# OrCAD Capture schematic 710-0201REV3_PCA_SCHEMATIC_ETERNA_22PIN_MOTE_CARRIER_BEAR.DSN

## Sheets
1 01) Title: title: PCA SCHEMATIC, ETERNA 22-PIN WH MOTE, BEAR; rev: 03; note: 710-0201
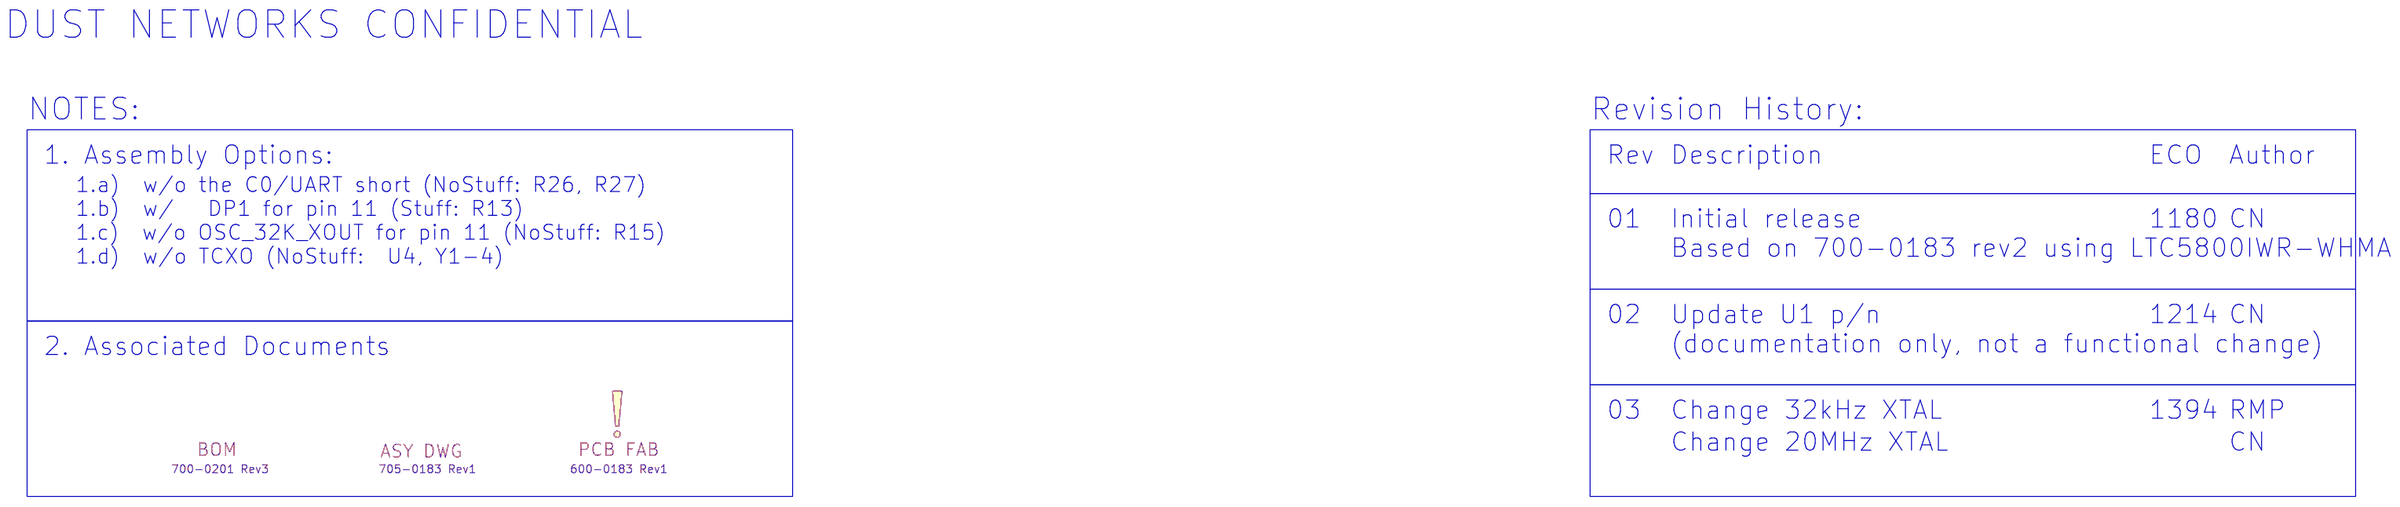
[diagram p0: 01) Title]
2 02) OSKI Mote: size Custom
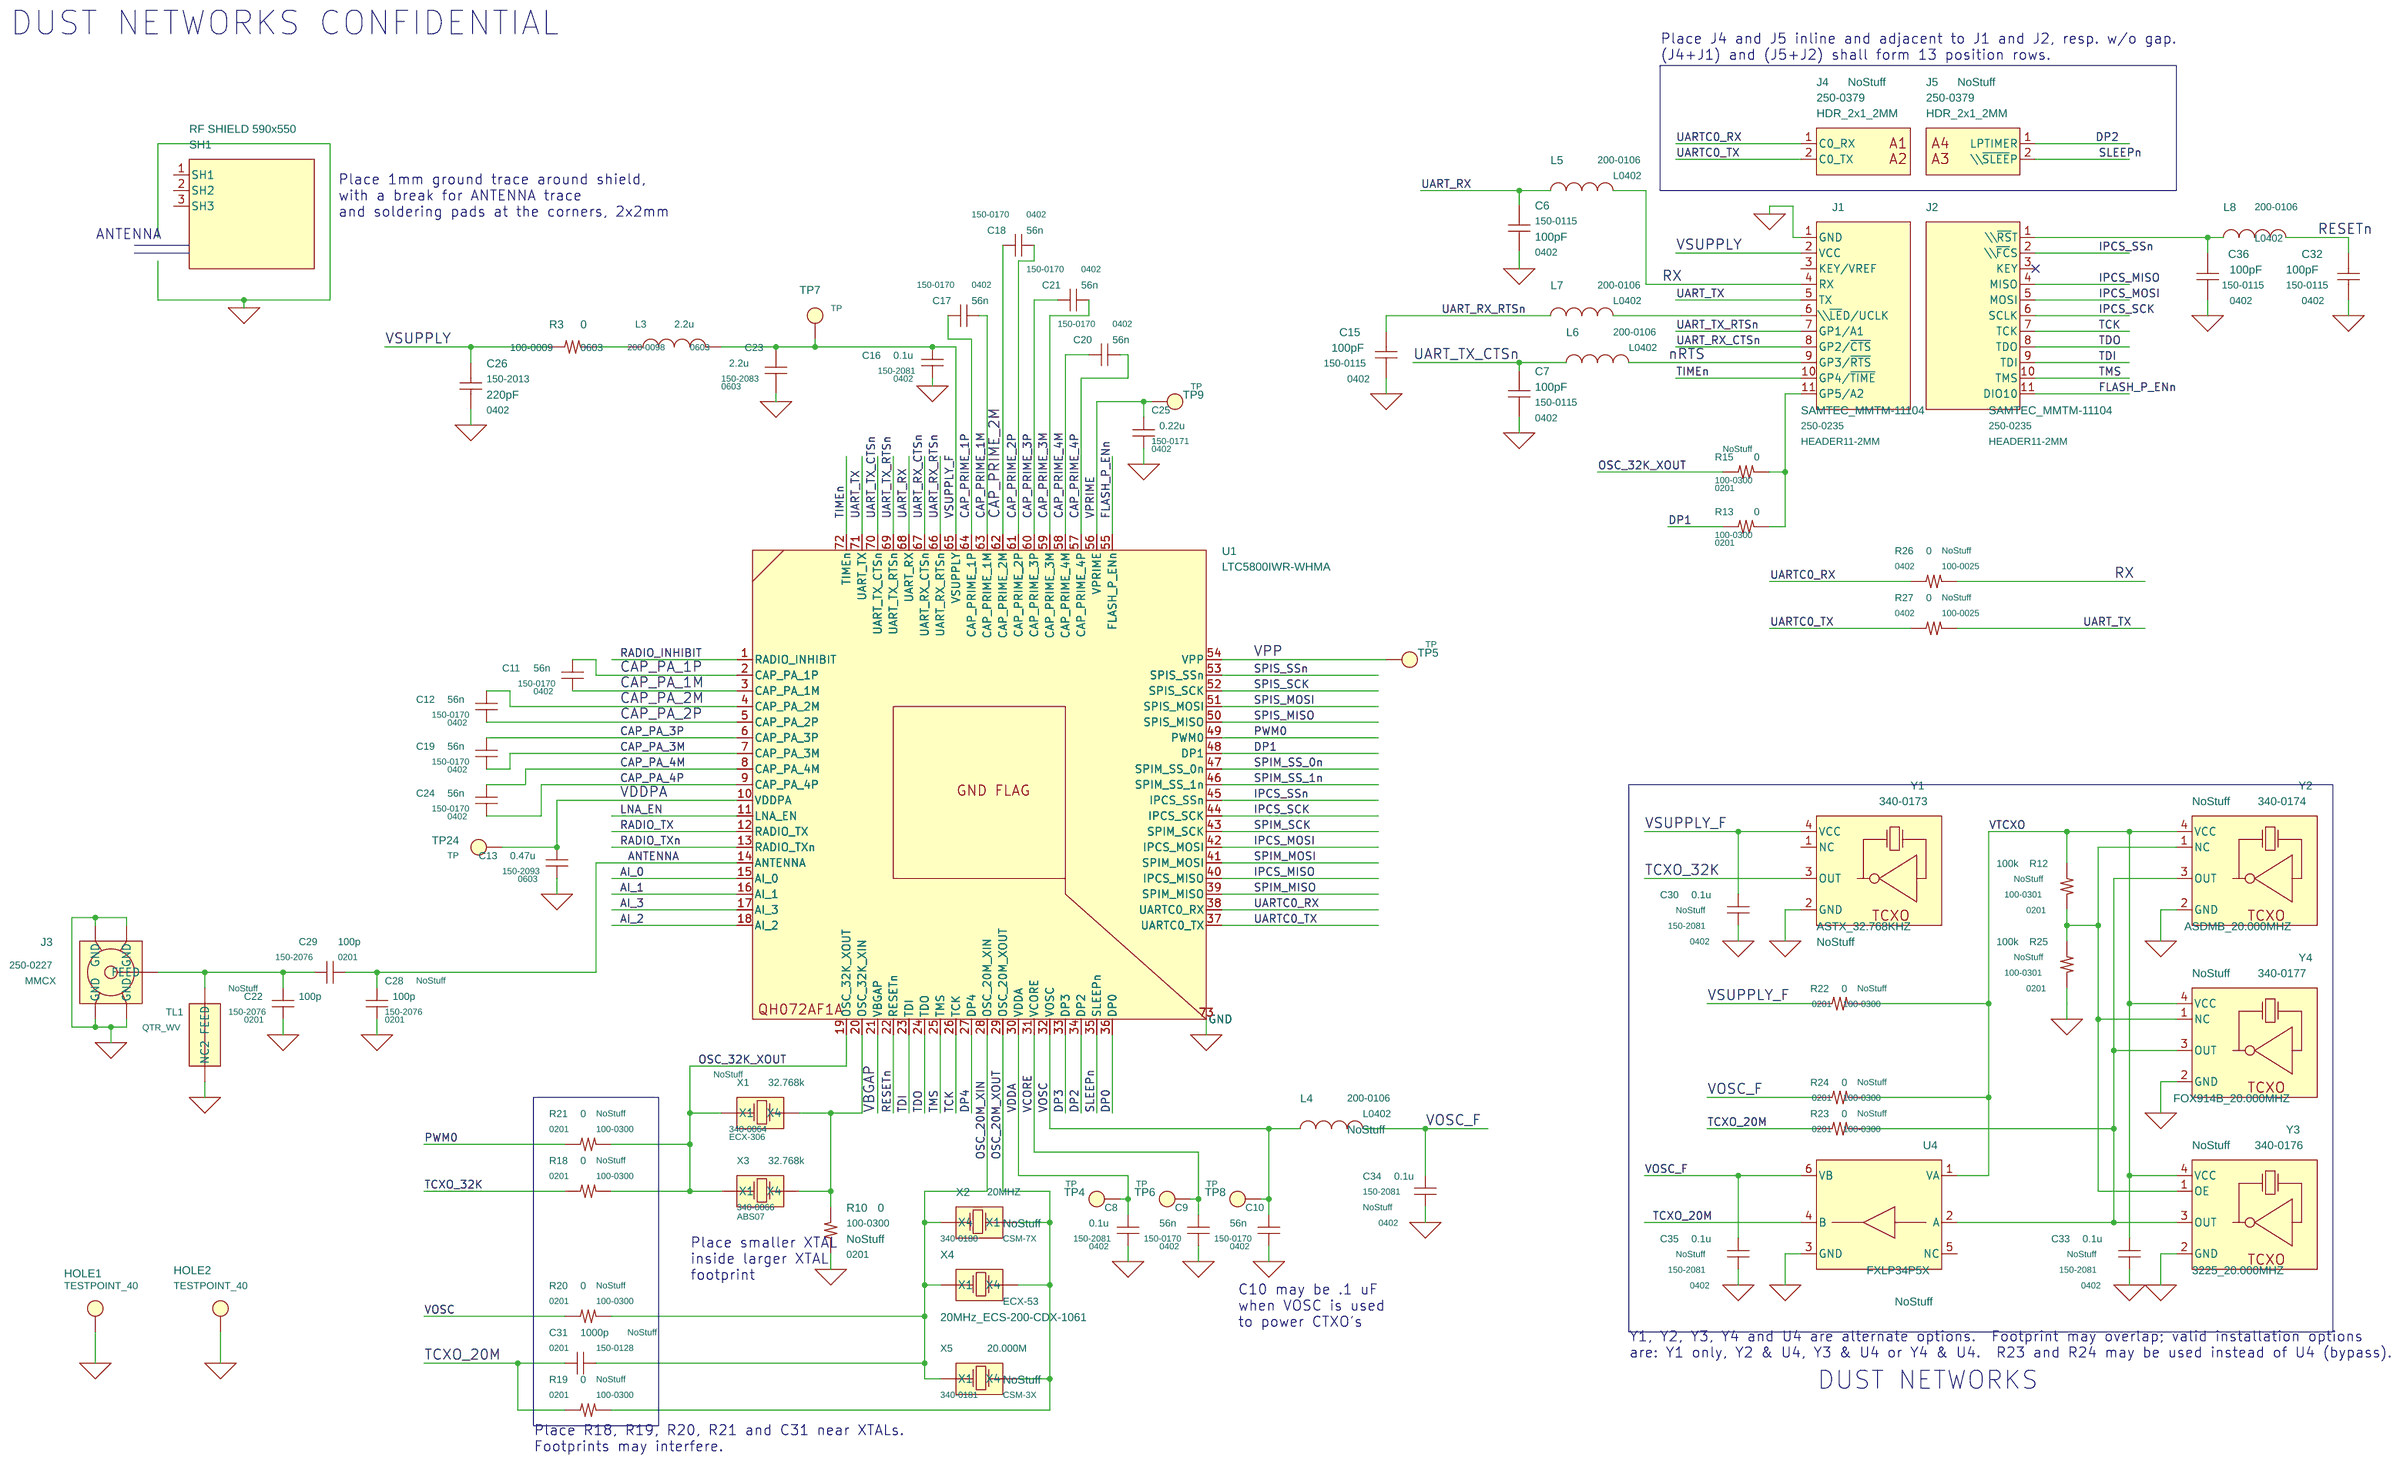
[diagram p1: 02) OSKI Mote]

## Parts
sheet 01) Title
WARNINGL11  CALLOUT_PCB_FAB
WARNINGL12  CALLOUT_BOM
WARNINGL13  CALLOUT_ASSY_DWG
sheet 02) OSKI Mote
C6  100pF  [0402]
C7  100pF  [0402]
C8  0.1u  [0402]
C9  56n  [0402]
C10  56n  [0402]
C11  56n  [0402]
C12  56n  [0402]
C13  0.47u  [0603]
C15  100pF  [0402]
C16  0.1u  [0402]
C17  56n  [0402]
C18  56n  [0402]
C19  56n  [0402]
C20  56n  [0402]
C21  56n  [0402]
C22  100p  [0201]
C23  2.2u  [0603]
C24  56n  [0402]
C25  0.22u  [0402]
C26  220pF  [0402]
C28  100p  [0201]
C29  100p  [0201]
C30  0.1u  [0402]
C31  1000p  [0201]
C32  100pF  [0402]
C33  0.1u  [0402]
C34  0.1u  [0402]
C35  0.1u  [0402]
C36  100pF  [0402]
HOLE1  HOLE  [TESTPOINT_40]
HOLE2  HOLE  [TESTPOINT_40]
J1  SAMTEC_MMTM-11104  [HEADER11-2MM]
J2  SAMTEC_MMTM-11104  [HEADER11-2MM]
J3  MMCX/U.FL  [MMCX]
J4  HDR_2x1_2MM  [HDR2X1PTH2MM_RND]
J5  HDR_2x1_2MM  [HDR2X1PTH2MM_RND]
L3  2.2u  [0603]
L4  200mA_600mO  [L0402]
L5  200mA_600mO  [L0402]
L6  200mA_600mO  [L0402]
L7  200mA_600mO  [L0402]
L8  200mA_600mO  [L0402]
R3  0  [0603]
R10  0  [0201]
R12  100k  [0201]
R13  0  [0201]
R15  0  [0201]
R18  0  [0201]
R19  0  [0201]
R20  0  [0201]
R21  0  [0201]
R22  0  [0201]
R23  0  [0201]
R24  0  [0201]
R25  100k  [0201]
R26  0  [0402]
R27  0  [0402]
SH1  RF SHIELD 590x550  [SHLD_BEAR]
TL1  FR05  [QTR_WV]
TP4  TP 35Mil  [TP]
TP5  TP 35Mil  [TP]
TP6  TP 35Mil  [TP]
TP7  TP 35Mil  [TP]
TP8  TP 35Mil  [TP]
TP9  TP 35Mil  [TP]
TP24  TP 35Mil  [TP]
U1  LTC5800IWR-WHMA  [QH072AF1A]
U4  FXLP34P5X  [SC70]
X1  32.768k  [ECX-306]
X2  20MHZ  [CSM-7X]
X3  32.768k  [ABS07]
X4  20MHz_ECS-200-CDX-1061  [ECX-53]
X5  20.000M  [CSM-3X]
Y1  ASTX_32.768KHZ  [XASTX7050SM]
Y2  ASDMB_20.000MHZ  [XASDMB2520SM]
Y3  3225_20.000MHZ  [XTAL3225SM]
Y4  FOX914B_20.000MHZ  [XFOX5032SM]

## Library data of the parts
WARNINGL11 = CALLOUT_PCB_FAB: Part Number: 600-0183 Rev1
WARNINGL12 = CALLOUT_BOM: Part Number: 700-0201 Rev3
WARNINGL13 = CALLOUT_ASSY_DWG: Part Number: 705-0183 Rev1
C6 C7 C15 C32 C36 = CAP_NP_5: P/N #1: GRM188F51A475ZE20; Part Number: 150-0115; Rating: 50V; Tolerance: 5%
C8 = C_Generic: Mfg #1: Murata; Mfg #2: GRM033R60J104KE19D; P/N #1: 150-FIX; Part Number: 150-2081; Rating: 16V; Tolerance: 10%
C9 C10 = C_Generic: Mfg #1: Murata; Mfg #2: GRM033R60J104KE19D; P/N #1: 150-FIX; Part Number: 150-0170; Rating: 16V; Tolerance: 10%
C11 C12 C17-C21 C24 = C_Generic: Mfg #1: Murata; Mfg #2: GRM033R60J104KE19D; P/N #1: 150-2081; Part Number: 150-0170; Rating: 16V; Tolerance: 10%
C13 = C_Generic: Mfg #1: Murata; Mfg #2: GRM033R60J104KE19D; P/N #1: 150-2081; Part Number: 150-2093; Rating: 16V; Tolerance: 10%
C16 = C_Generic: Mfg #1: Murata; Mfg #2: GRM033R60J104KE19D; P/N #1: 150-2081; Part Number: 150-2081; Rating: 16V; Tolerance: 10%
C22 C28 = C_Generic: Mfg #1: Murata; Mfg #2: GRM033R60J104KE19D; P/N #1: 150-FIX; Part Number: 150-2076; Rating: 16V; Stuff: NoStuff; Tolerance: 10%
C23 = CAP_NP_5: P/N #1: GRM188R71A225KE15D; Part Number: 150-2083; Rating: 10V; Tolerance: 10%
C25 = C_Generic: Mfg #1: Murata; Mfg #2: GRM033R60J104KE19D; P/N #1: 150-FIX; Part Number: 150-0171; Rating: 16V; Tolerance: 10%
C26 = CAP_NP_5: P/N #1: GRM188F51A475ZE20; Part Number: 150-2013; Rating: 6.3V; Tolerance: 20%
C29 = C_Generic: Mfg #1: Murata; Mfg #2: GRM033R60J104KE19D; P/N #1: 150-FIX; Part Number: 150-2076; Rating: 16V; Tolerance: 10%
C30 C33-C35 = C_Generic: Mfg #1: Murata; Mfg #2: GRM033R60J104KE19D; P/N #1: 150-2081; Part Number: 150-2081; Rating: 16V; Stuff: NoStuff; Tolerance: 10%
C31 = C_Generic: Mfg #1: Murata; Mfg #2: GRM033R60J104KE19D; P/N #1: 150-FIX; Part Number: 150-0128; Rating: 16V; Stuff: NoStuff; Tolerance: 10%
HOLE1 HOLE2 = Mighty_GND_0: Manuf PN: NA
J1 = hdr1x8_5: Manuf PN: Samtec MTMM-111-04-S-S-175-3; Part Number: 250-0235
J2 = hdr1x8_4: Manuf PN: Samtec MTMM-111-04-S-S-175-3; Part Number: 250-0235
J3 = Hirose_EFL_4: CONN MMCX JACK STR PCB .115" GOLD; Alternate: Johnson 135-3701-301 (MMCX RA), JST AYU1-1P-02676-120 (U.FL); Dist PN: Digikey J597-ND; Manuf PN: Johnson 135-3701-201; Part Number: 250-0227
J4 = HDR_2x1_2MM_PTHRND_A1A2: Color: Default; Part Number: 250-0379; Stuff: NoStuff
J5 = HDR_2x1_2MM_PTHRND_A4A3: Color: Default; Part Number: 250-0379; Stuff: NoStuff
L3 = INDUCTOR: P/N #1: LQM18FN2R2K00; Part Number: 200-0098; Tolerance: 10%
L4 = IND_FERRITE_200MA_470OHM_0402: Part Number: 200-0106; Stuff: NoStuff
L5-L8 = IND_FERRITE_200MA_470OHM_0402: Part Number: 200-0106
R3 = R_Small: P/N #1: 100-0058; Part Number: 100-0009; Rating: 1/16 W; Tolerance: 5%
R10 = R_Small: P/N #1: 100-0058; Part Number: 100-0300; Rating: 1/16 W; Stuff: NoStuff; Tolerance: 5%
R12 R25 = R_Small: Mfg #1: Panasonic; Mfg #2: ERJ-1GEJ104C; P/N #1: 100-0048; Part Number: 100-0301; Rating: 1/16 W; Stuff: NoStuff; Tolerance: 5%
R13 = R_Small: Mfg #1: Panasonic; Mfg #2: ERJ-1GEJ104C; P/N #1: 100-0048; Part Number: 100-0300; Rating: 1/16 W; Tolerance: 5%
R15 R18-R24 = R_Small: Mfg #1: Panasonic; Mfg #2: ERJ-1GEJ104C; P/N #1: 100-0048; Part Number: 100-0300; Rating: 1/16 W; Stuff: NoStuff; Tolerance: 5%
R26 R27 = R_Small: Mfg #1: Yageo; Mfg #2: RC0402JR-070RL; P/N #1: 100-0048; Part Number: 100-0025; Rating: 1/16 W; Stuff: NoStuff; Tolerance: 5%
SH1 = BEAR_SHIELD
TL1 = Hirose_EFL_8: CONN MMCX JACK STR PCB .115" GOLD; Alternate: Johnson 135-3701-301 (MMCX RA), JST AYU1-1P-02676-120 (U.FL); Dist PN: Digikey J597-ND; Manuf PN: Johnson 135-3701-201
TP4-TP9 TP24 = TP35: Dist PN: NA; Manuf PN: NA
U1 = LTC5800IWR-WHMA
U4 = FXLP34P5X_SC70: Stuff: NoStuff
X1 = CITIZEN4_0: Mfg #1: Suntsu; Part Number: 340-0064; Stuff: NoStuff
X2 = XTAL_20.000MHZ_CTRL_ECS-CSM7X: CRYSTAL, 20.000MHZ, 10PF, +/-10PPM, +/-30PPM STAB, CONTROLED T CURVE, 13.2X4.8X4.3MM, CSM-7X, SMT, ECS-200-CDX-0912; Part Number: 340-0180; Stuff: NoStuff
X3 = CITIZEN4_0: Mfg #1: Suntsu; Part Number: 340-0066
X4 = XTAL_20.000MHZ_ECS-200-CDX-1061
X5 = XTAL_20.000MHZ_CRTL_ECS-CSM3X: CRYSTAL, 20.000MHZ, 10PF, +/-10PPM, +/-30PPM STAB, CONTROLED T CURVE, 7.6X4.1X2.3MM, CSM-3X, SMT, ECS-200-CDX-0914; Part Number: 340-0181; Stuff: NoStuff
Y1 = TCXO_32.768KHZ_ASTX-H08K_SM7X5: Part Number: 340-0173; Stuff: NoStuff
Y2 = TCXO_20.000MHZ_MEMS_ASDMB-XY: Part Number: 340-0174; Stuff: NoStuff
Y3 = TCXO_20.000MHZ_XTAL3225SM: OSC, TCXO 20.000MHZ, 5PPM, -40/85C, 3.3V, SMT, 2.5x3.2MM, ECS-2532HS (ALT: FOX923, ABRACON ASEMP); Part Number: 340-0176; Stuff: NoStuff
Y4 = TCXO_20.000MHZ_FOX914B: Part Number: 340-0177; Stuff: NoStuff

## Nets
GND_SIGNAL: C6.1 C7.1 C8.2 C9.2 C10.2 C13.2 C15.1 C16.2 C22.2 C23.2 C25.2 C26.1 C28.2 C30.2 C32.1 C33.2 C34.2 C35.2 C36.1 HOLE1.1(TP) HOLE2.1(TP) J1.1(GND) J3.2(GND) J3.3(GND) J3.4(GND) J3.5(GND) R10.1 R25.1 TL1.2(NC2) U1.73(GND) U4.3(GND) Y1.2(GND) Y2.2(GND) Y3.2(GND) Y4.2(GND)
VDDA: C8.1 TP4.1(TP) U1.30(VDDA)
VDDPA: C13.1 TP24.1(TP) U1.10(VDDPA)
AI_0: U1.15(AI_0)
AI_1: U1.16(AI_1)
AI_2: U1.18(AI_2)
AI_3: U1.17(AI_3)
ANTENNA: C28.1 C29.2 U1.14(ANTENNA)
CAP_PA_1M: C11.2 U1.3(CAP_PA_1M)
CAP_PA_1P: C11.1 U1.2(CAP_PA_1P)
CAP_PA_2M: C12.1 U1.4(CAP_PA_2M)
CAP_PA_2P: C12.2 U1.5(CAP_PA_2P)
CAP_PA_3M: C19.2 U1.7(CAP_PA_3M)
CAP_PA_3P: C19.1 U1.6(CAP_PA_3P)
CAP_PA_4M: C24.1 U1.8(CAP_PA_4M)
CAP_PA_4P: C24.2 U1.9(CAP_PA_4P)
CAP_PRIME_1M: C17.2 U1.63(CAP_PRIME_1M)
CAP_PRIME_1P: C17.1 U1.64(CAP_PRIME_1P)
CAP_PRIME_2M: C18.1 U1.62(CAP_PRIME_2M)
CAP_PRIME_2P: C18.2 U1.61(CAP_PRIME_2P)
CAP_PRIME_3M: C21.2 U1.59(CAP_PRIME_3M)
CAP_PRIME_3P: C21.1 U1.60(CAP_PRIME_3P)
CAP_PRIME_4M: C20.1 U1.58(CAP_PRIME_4M)
CAP_PRIME_4P: C20.2 U1.57(CAP_PRIME_4P)
DP0: U1.36(DP0)
DP1: R13.1 U1.48(DP1)
DP2: J5.1(LPTIMER) U1.34(DP2)
DP3: U1.33(DP3)
DP4: U1.27(DP4)
FLASH_P_ENn: J2.11(DIO10) U1.55(FLASH_P_ENn)
IPCS_MISO: J2.4(MISO) U1.40(IPCS_MISO)
IPCS_MOSI: J2.5(MOSI) U1.42(IPCS_MOSI)
IPCS_SCK: J2.6(SCLK) U1.44(IPCS_SCK)
IPCS_SSn: J2.2(\\~{FC}S) U1.45(IPCS_SSn)
LNA_EN: U1.11(LNA_EN)
nRTS: J1.9(GP3/~{RTS}) L6.2
OSC_20M_XIN: C31.2 R20.2 U1.28(OSC_20M_XIN) X2.2(X4) X4.1(X1) X5.1(X1)
OSC_20M_XOUT: R19.2 U1.29(OSC_20M_XOUT) X2.1(X1) X4.2(X4) X5.2(X4)
OSC_32K_XOUT: R15.1 R18.2 R21.2 U1.19(OSC_32K_XOUT) X1.1(X1) X3.1(X1)
PWM0: R21.1 U1.49(PWM0)
RADIO_INHIBIT: U1.1(RADIO_INHIBIT)
RADIO_TX: U1.12(RADIO_TX)
RADIO_TXn: U1.13(RADIO_TXn)
RESETn: C32.2 L8.2 U1.22(RESETn)
RX: J1.4(RX) L5.2 R26.2
SLEEPn: J5.2(\\~{SLEE}P) U1.35(SLEEPn)
SPIM_MISO: U1.39(SPIM_MISO)
SPIM_MOSI: U1.41(SPIM_MOSI)
SPIM_SCK: U1.43(SPIM_SCK)
SPIM_SS_0n: U1.47(SPIM_SS_0n)
SPIM_SS_1n: U1.46(SPIM_SS_1n)
SPIS_MISO: U1.50(SPIS_MISO)
SPIS_MOSI: U1.51(SPIS_MOSI)
SPIS_SCK: U1.52(SPIS_SCK)
SPIS_SSn: U1.53(SPIS_SSn)
TCK: J2.7(TCK) U1.26(TCK)
TCXO_20M: C31.1 R19.1 R23.1 U4.4(B)
TCXO_32K: R18.1 Y1.3(OUT)
TDI: J2.9(TDI) U1.23(TDI)
TDO: J2.8(TDO) U1.24(TDO)
TIMEn: J1.10(GP4/~{TIME}) U1.72(TIMEn)
TMS: J2.10(TMS) U1.25(TMS)
UART_RX: C6.2 L5.1 U1.68(UART_RX)
UART_RX_CTSn: J1.8(GP2/~{CTS}) U1.67(UART_RX_CTSn)
UART_RX_RTSn: C15.2 L7.1 U1.66(UART_RX_RTSn)
UART_TX: J1.5(TX) R27.2 U1.71(UART_TX)
UART_TX_CTSn: C7.2 L6.1 U1.70(UART_TX_CTSn)
UART_TX_RTSn: J1.7(GP1/A1) U1.69(UART_TX_RTSn)
UARTC0_RX: J4.1(C0_RX) R26.1 U1.38(UARTC0_RX)
UARTC0_TX: J4.2(C0_TX) R27.1 U1.37(UARTC0_TX)
VBGAP: U1.21(VBGAP)
VCORE: C9.1 TP6.1(TP) U1.31(VCORE)
VOSC: C10.1 L4.1 R20.1 TP8.1(TP) U1.32(VOSC)
VOSC_F: C34.1 C35.1 L4.2 R24.1 U4.6(VB)
VPP: TP5.1(TP) U1.54(VPP)
VPRIME: C25.1 TP9.1(TP) U1.56(VPRIME)
VSUPPLY: C26.2 J1.2(VCC) R3.1
VSUPPLY_F: C16.1 C23.1 C30.1 L3.2 R22.1 TP7.1(TP) U1.65(VSUPPLY) Y1.4(VCC)
VTCXO: C33.1 R12.2 R22.2 R24.2 U4.1(VA) Y2.4(VCC) Y3.4(VCC) Y4.4(VCC)
N17907381: J1.11(GP5/A2) R13.2 R15.2
N19117367: L3.1 R3.2
N19117458: R10.2 U1.20(OSC_32K_XIN) X1.2(X4) X3.2(X4)
N19117741: C22.1 C29.1 J3.1(FEED) TL1.1(FEED)
N19224637: J1.6(\\~{LE}D/UCLK) L7.2
N19546026: R23.2 U4.2(A) Y2.3(OUT) Y3.3(OUT) Y4.3(OUT)
N19766592: R12.1 R25.2 Y2.1(NC) Y3.1(OE) Y4.1(NC)
N19836942: C36.2 J2.1(\\~{RS}T) L8.1

Not connected (* = marked no-connect by the designer): J1 3(KEY/VREF); J2 3(KEY)*; SH1 1(SH1) 2(SH2) 3(SH3); U4 5(NC); Y1 1(NC)

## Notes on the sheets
sheet 1
- DUST NETWORKS CONFIDENTIAL
- NOTES:
- Revision History:
- 1. Assembly Options:
- Rev
- Description
- ECO
- Author
- 1.a)  w/o the C0/UART short (NoStuff: R26, R27)
  1.b)  w/   DP1 for pin 11 (Stuff: R13)
  1.c)  w/o OSC_32K_XOUT for pin 11 (NoStuff: R15)
  1.d)  w/o TCXO (NoStuff:  U4, Y1-4)
- 01
- Initial release
  Based on 700-0183 rev2 using LTC5800IWR-WHMA
- 1180
- CN
- 02
- Update U1 p/n
  (documentation only, not a functional change)
- 1214
- CN
- 2. Associated Documents
- 03
- Change 32kHz XTAL
- 1394
- RMP
- Change 20MHz XTAL
- CN
sheet 2
- DUST NETWORKS CONFIDENTIAL
- Place J4 and J5 inline and adjacent to J1 and J2, resp. w/o gap.
  (J4+J1) and (J5+J2) shall form 13 position rows.
- Place 1mm ground trace around shield,
  with a break for ANTENNA trace
  and soldering pads at the corners, 2x2mm
- ANTENNA
- Place smaller XTAL
  inside larger XTAL
  footprint
- C10 may be .1 uF
  when VOSC is used
  to power CTXO's
- Y1, Y2, Y3, Y4 and U4 are alternate options.  Footprint may overlap; valid installation options
  are: Y1 only, Y2 & U4, Y3 & U4 or Y4 & U4.  R23 and R24 may be used instead of U4 (bypass).
- DUST NETWORKS
- Place R18, R19, R20, R21 and C31 near XTALs.
  Footprints may interfere.
